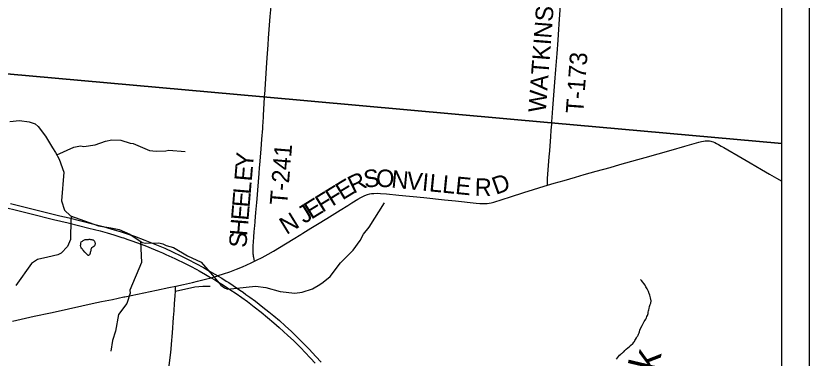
# Model space of a CAD drawing. Extents: x -5.4 to 49.9, y 13.2 to 48.4.
# Drawn here: x 30.593 to 33.165, y 43.736 to 44.845 of the extents above; entities that cross this region are included whole.
import ezdxf

# ---------------------------------------------------------------- set-up
doc = ezdxf.new("R2010")
doc.units = 0
for name, color, linetype in [('GM_X_County_Road', 7, 'Continuous'), ('GM_X_County_Road_Text', 7, 'Continuous'), ('GM_X_Minor_Lake', 7, 'Continuous'), ('GM_X_Minor_River', 7, 'Continuous'), ('GM_X_Minor_River_Text', 7, 'Continuous'), ('GM_X_Township', 7, 'Continuous'), ('GM_X_Township_Road', 7, 'Continuous'), ('GM_X_Township_Road_Text', 7, 'Continuous'), ('GM_X_US_Route', 7, 'Continuous'), ('SH_Data', 7, 'Continuous')]:
    doc.layers.add(name, color=color, linetype=linetype)

msp = doc.modelspace()

# ---------------------------------------------------------------- linework, layer by layer
at = {"layer": 'GM_X_County_Road'}
for points in [[(32.3165, 44.2958), (32.3385, 44.3026), (32.3708, 44.3117), (32.4079, 44.3222), (32.436, 44.3303), (32.4748, 44.3413), (32.5197, 44.3539), (32.5519, 44.3631), (32.6099, 44.3796), (32.6339, 44.3863), (32.6752, 44.3978), (32.7176, 44.4098), (32.7619, 44.4222), (32.7929, 44.4313), (32.8073, 44.4353), (32.8164, 44.4376), (32.8222, 44.4388), (32.8281, 44.4397), (32.8329, 44.44), (32.8376, 44.44), (32.8417, 44.4395), (32.8464, 44.4387), (32.85, 44.4378), (32.8542, 44.4365), (32.8595, 44.4344), (32.8652, 44.4317), (32.8717, 44.428), (32.8803, 44.423), (32.8884, 44.4183), (32.9479, 44.3834), (32.9742, 44.3681), (33.0108, 44.347), (33.0371, 44.3317), (33.0592, 44.319), (33.0771, 44.3087)], [(31.5172, 44.1369), (31.5231, 44.1405), (31.549, 44.1565), (31.5707, 44.1699), (31.6015, 44.1887), (31.6443, 44.2151), (31.6697, 44.2307), (31.6829, 44.2389), (31.702, 44.2507), (31.7117, 44.2563), (31.7206, 44.2608), (31.7246, 44.2626), (31.7328, 44.2657), (31.7407, 44.2677), (31.7463, 44.2688), (31.7537, 44.2698), (31.7644, 44.2701), (31.7756, 44.2696), (31.7948, 44.268), (31.8351, 44.2643), (31.916, 44.2558), (31.9828, 44.249), (32.018, 44.2455), (32.086, 44.2384), (32.0977, 44.2372), (32.107, 44.2366), (32.115, 44.2365), (32.1212, 44.2368), (32.1279, 44.2377), (32.1345, 44.239), (32.1428, 44.2413), (32.1967, 44.2583), (32.2406, 44.2722), (32.2714, 44.282), (32.3058, 44.2925), (32.3165, 44.2958)], [(31.3668, 44.0496), (31.3737, 44.0529), (31.3919, 44.0623), (31.411, 44.0727), (31.4282, 44.0826), (31.4479, 44.0944), (31.4923, 44.1218), (31.5172, 44.1369)], [(31.1112, 43.9695), (31.1368, 43.9749), (31.166, 43.981), (31.1823, 43.9847), (31.2076, 43.9912), (31.226, 43.9962), (31.2291, 43.9971), (31.2477, 44.0027), (31.2494, 44.0031), (31.2659, 44.0085), (31.287, 44.0159), (31.3085, 44.024), (31.3275, 44.0316), (31.3418, 44.0377), (31.3564, 44.0445), (31.3668, 44.0496)], [(30.9468, 43.9347), (30.9666, 43.9389), (31.0487, 43.9563), (31.0888, 43.9648), (31.1112, 43.9695)], [(30.5815, 43.8559), (30.6526, 43.8713), (30.7054, 43.883), (30.7303, 43.8884), (30.8401, 43.9127), (30.8705, 43.919), (30.9064, 43.9262), (30.9429, 43.9339), (30.9468, 43.9347)]]:
    msp.add_lwpolyline(points, dxfattribs=at)
at = {"layer": 'GM_X_Minor_Lake'}
msp.add_lwpolyline([(30.8274, 44.0679), (30.8161, 44.079), (30.8116, 44.0859), (30.8094, 44.0882), (30.8075, 44.0898), (30.8052, 44.0925), (30.8045, 44.0948), (30.8038, 44.0967), (30.803, 44.1009), (30.8031, 44.1035), (30.8031, 44.1054), (30.8035, 44.1081), (30.8051, 44.1122), (30.8066, 44.1141), (30.8085, 44.1152), (30.8112, 44.1171), (30.8131, 44.1182), (30.815, 44.119), (30.8177, 44.1197), (30.8199, 44.12), (30.8222, 44.1204), (30.8249, 44.1204), (30.8283, 44.1207), (30.8302, 44.1211), (30.8325, 44.121), (30.8347, 44.1206), (30.837, 44.1206), (30.8389, 44.1202), (30.8416, 44.1194), (30.8435, 44.119), (30.8461, 44.1171), (30.8483, 44.1144), (30.8494, 44.1106), (30.8505, 44.1079), (30.8505, 44.1053), (30.8493, 44.1026), (30.8474, 44.0996), (30.8455, 44.0977), (30.8421, 44.0955), (30.8402, 44.094), (30.8379, 44.0929), (30.8371, 44.0902), (30.8363, 44.0876), (30.8355, 44.0834), (30.8351, 44.0815), (30.8343, 44.0781), (30.8335, 44.0754), (30.8327, 44.0724), (30.8312, 44.0701), (30.8289, 44.0683), (30.8274, 44.0679)], dxfattribs=at)
at = {"layer": 'GM_X_Minor_River'}
for points in [[(30.5732, 44.5029), (30.6044, 44.5058), (30.6357, 44.5018), (30.6553, 44.4953), (30.665, 44.4868), (30.6891, 44.4548), (30.7119, 44.4168), (30.7219, 44.4018), (30.7332, 44.3803), (30.748, 44.3379), (30.7411, 44.2457), (30.7504, 44.2148), (30.7698, 44.1973), (30.8609, 44.1649), (30.9009, 44.1577), (30.9274, 44.1523), (30.9627, 44.1376), (31.0024, 44.1103), (31.0145, 44.1082), (31.057, 44.1093), (31.069, 44.1057), (31.0807, 44.1013), (31.1037, 44.094), (31.1498, 44.0673), (31.1934, 44.0472), (31.2302, 44.0051), (31.2573, 43.9727), (31.2693, 43.9634), (31.2794, 43.9598), (31.3702, 43.9688), (31.4034, 43.9651), (31.4498, 43.9521), (31.4971, 43.9467), (31.5214, 43.95), (31.5549, 43.9601), (31.5791, 43.9748), (31.5894, 43.9819), (31.6121, 44.0001), (31.6459, 44.0443), (31.6868, 44.0857), (31.7093, 44.1168), (31.7207, 44.1379), (31.7381, 44.1603), (31.788, 44.2388)], [(30.7256, 44.3948), (30.7813, 44.419), (30.803, 44.4239), (30.8128, 44.4218), (30.8504, 44.4268), (30.884, 44.4384), (30.9045, 44.4429), (30.9333, 44.4424), (30.9634, 44.432), (30.9737, 44.4318), (31.0267, 44.4088), (31.0483, 44.4069), (31.079, 44.4071), (31.0889, 44.41), (31.1422, 44.4056)], [(30.7741, 44.1958), (30.7711, 44.1859), (30.7703, 44.1206), (30.7604, 44.0972), (30.7399, 44.0756), (30.7285, 44.0701), (30.6961, 44.0627), (30.6634, 44.0549), (30.6435, 44.042), (30.5933, 43.9711)], [(30.9976, 44.1136), (31.0001, 44.0454), (30.9625, 43.9564), (30.9631, 43.9458), (30.953, 43.9125), (30.9255, 43.8773), (30.9155, 43.8236), (30.9058, 43.7926), (30.9014, 43.7589)], [(32.5411, 43.7324), (32.5438, 43.7366), (32.5473, 43.7411), (32.5508, 43.7449), (32.5542, 43.7483), (32.5573, 43.7505), (32.5592, 43.7516), (32.5623, 43.755), (32.5645, 43.7561), (32.568, 43.7603), (32.5718, 43.7644), (32.5772, 43.7693), (32.5826, 43.773), (32.5864, 43.7764), (32.594, 43.7828), (32.5952, 43.7847), (32.5971, 43.7873), (32.5987, 43.7896), (32.6006, 43.793), (32.6025, 43.7967), (32.6052, 43.8016), (32.6079, 43.8054), (32.6099, 43.8081), (32.611, 43.8103), (32.6122, 43.8133), (32.6134, 43.816), (32.6141, 43.8179), (32.6149, 43.8205), (32.6165, 43.8262), (32.6196, 43.8338), (32.6235, 43.8417), (32.6274, 43.8485), (32.6308, 43.8542), (32.6332, 43.8583), (32.6355, 43.8625), (32.6374, 43.8663), (32.6394, 43.8708), (32.6409, 43.8738), (32.6421, 43.8768), (32.6429, 43.8803), (32.6437, 43.8844), (32.6449, 43.8886), (32.6457, 43.892), (32.6465, 43.8962), (32.6481, 43.9026), (32.65, 43.9098), (32.6524, 43.9143), (32.6532, 43.9219), (32.6514, 43.9315), (32.6488, 43.9402), (32.647, 43.9452), (32.6459, 43.9471), (32.6451, 43.949), (32.6444, 43.9513), (32.6425, 43.9555), (32.6403, 43.9601), (32.6381, 43.9635), (32.6362, 43.967), (32.6336, 43.9719), (32.622, 43.9873), (32.6198, 43.9896), (32.6186, 43.99), (32.6186, 43.99)]]:
    msp.add_lwpolyline(points, dxfattribs=at)
at = {"layer": 'GM_X_Township'}
for points in [[(28.0105, 47.4437), (27.6877, 47.1657), (27.6499, 47.1327), (27.6308, 47.1161), (28.089, 46.5424), (27.3995, 45.9845), (27.4216, 45.9826), (27.5161, 45.979), (27.573, 45.9769), (27.6274, 45.9769), (27.7195, 46.0028), (27.6935, 45.0509), (27.691, 44.9621), (27.6878, 44.8437), (27.7914, 44.8377), (29.42, 44.7443), (29.8881, 44.7175), (31.3945, 44.5822), (32.3292, 44.4982), (33.0771, 44.431)], [(33.0771, 44.431), (33.0771, 47.4437), (28.0105, 47.4437)], [(33.0771, 44.431), (32.3292, 44.4982), (31.3945, 44.5822), (29.8881, 44.7175)], [(31.4373, 40.6437), (33.0771, 40.6437), (33.0771, 44.431)]]:
    msp.add_lwpolyline(points, dxfattribs=at)
at = {"layer": 'GM_X_Township_Road'}
for points in [[(31.3997, 44.586), (31.4, 44.5899), (31.4035, 44.6413), (31.4057, 44.6767), (31.4078, 44.7089), (31.4109, 44.7511), (31.4125, 44.7727), (31.4158, 44.8142), (31.4179, 44.8431), (31.4204, 44.8749)], [(32.3313, 44.5022), (32.3323, 44.5158), (32.3344, 44.5456), (32.3377, 44.5877), (32.3409, 44.6304), (32.3442, 44.6713), (32.3481, 44.7234), (32.3513, 44.7661), (32.3526, 44.7847), (32.3561, 44.8337), (32.3593, 44.8789)], [(31.3945, 44.5001), (31.3956, 44.518), (31.3972, 44.5465), (31.3979, 44.557), (31.3997, 44.586)], [(32.3265, 44.4384), (32.3276, 44.4532), (32.3292, 44.4743), (32.3307, 44.4941), (32.3313, 44.5022)], [(31.3671, 44.1581), (31.3674, 44.1618), (31.3689, 44.1792), (31.3713, 44.2077), (31.3739, 44.2399), (31.3749, 44.2516), (31.3774, 44.2801), (31.3796, 44.3073), (31.3819, 44.3346), (31.3834, 44.3532), (31.384, 44.3612), (31.3872, 44.4015), (31.3881, 44.4132), (31.3905, 44.4448), (31.3933, 44.4801), (31.3938, 44.4875), (31.3945, 44.5001)], [(32.3165, 44.2958), (32.3166, 44.2991), (32.3167, 44.3042), (32.3169, 44.3098), (32.3171, 44.3143), (32.3172, 44.3176), (32.3194, 44.346), (32.3226, 44.3882), (32.3242, 44.408), (32.3265, 44.4384)], [(31.3668, 44.0496), (31.3653, 44.0569), (31.3643, 44.0622), (31.3639, 44.0647), (31.3636, 44.0664), (31.3632, 44.0699), (31.3629, 44.0732), (31.3625, 44.0782), (31.3623, 44.0837), (31.3622, 44.0888), (31.3624, 44.0936), (31.3625, 44.0986), (31.3628, 44.103), (31.3631, 44.1092), (31.3648, 44.1309), (31.3659, 44.1433), (31.3671, 44.1581)], [(31.1061, 43.8887), (31.1078, 43.9131), (31.1095, 43.9379), (31.1109, 43.9532), (31.1108, 43.9546), (31.111, 43.9621), (31.1112, 43.9695)], [(31.1109, 43.9532), (31.1729, 43.967), (31.1988, 43.9694), (31.2234, 43.9689)], [(31.0609, 43.4913), (31.0618, 43.4981), (31.0639, 43.5135), (31.0675, 43.5425), (31.0717, 43.5733), (31.074, 43.5899), (31.0781, 43.6201), (31.0824, 43.6521), (31.0859, 43.6767), (31.0916, 43.7211), (31.0945, 43.7458), (31.0962, 43.765), (31.0975, 43.7811), (31.1004, 43.8176), (31.1045, 43.8672), (31.1061, 43.8887)]]:
    msp.add_lwpolyline(points, dxfattribs=at)
at = {"layer": 'GM_X_US_Route'}
for points in [[(30.5415, 44.228), (30.6127, 44.2105), (30.638, 44.204), (30.7147, 44.1853), (30.7623, 44.1737), (30.8293, 44.1572), (30.8661, 44.1478), (30.8888, 44.1416), (30.9103, 44.1353), (30.937, 44.1269), (30.9423, 44.1252), (30.9559, 44.1206), (30.9688, 44.1161), (30.9991, 44.1049), (31.0165, 44.0982), (31.0315, 44.0922), (31.0574, 44.0816), (31.0683, 44.0769), (31.0797, 44.072), (31.0983, 44.0634), (31.1084, 44.0586), (31.1196, 44.0532), (31.1336, 44.0464), (31.1587, 44.034), (31.1801, 44.0226), (31.1872, 44.0187), (31.2083, 44.0068), (31.2237, 43.9975), (31.226, 43.9962), (31.2377, 43.9893), (31.2498, 43.9818), (31.2657, 43.972), (31.2867, 43.9587), (31.3068, 43.9452), (31.3252, 43.9324), (31.3438, 43.9188), (31.366, 43.9019), (31.3881, 43.8846), (31.4088, 43.8678), (31.4292, 43.8505), (31.4465, 43.8354), (31.4751, 43.8095), (31.4928, 43.7929), (31.5083, 43.7777), (31.5184, 43.7676), (31.5302, 43.7555), (31.5485, 43.7361), (31.5637, 43.7196)], [(30.5755, 44.2366), (30.6322, 44.2225), (30.7354, 44.1974), (30.7656, 44.19), (30.8458, 44.1699), (30.8758, 44.1621), (30.9039, 44.1542), (30.9313, 44.146), (30.9537, 44.1387), (30.9772, 44.1306), (31.0116, 44.118), (31.033, 44.1097), (31.0543, 44.101), (31.0759, 44.0916), (31.1008, 44.0802), (31.1277, 44.0674), (31.1521, 44.0552), (31.1764, 44.0427), (31.201, 44.0294), (31.221, 44.0181), (31.2477, 44.0027), (31.249, 44.0019), (31.2611, 43.9945), (31.2753, 43.9855), (31.2831, 43.9805), (31.2977, 43.9709), (31.3193, 43.9563), (31.3295, 43.9493), (31.3391, 43.9424), (31.3511, 43.9337), (31.3696, 43.92), (31.3937, 43.9014), (31.4132, 43.886), (31.4295, 43.8726), (31.4474, 43.8572), (31.4664, 43.8402), (31.4864, 43.8217), (31.5084, 43.8007), (31.5292, 43.7801), (31.5444, 43.7646), (31.5661, 43.7415), (31.5832, 43.7227)]]:
    msp.add_lwpolyline(points, dxfattribs=at)
at = {"layer": 'SH_Data'}
msp.add_line((33.1653, 47.5483), (33.1653, 40.5483), dxfattribs=at)

# ---------------------------------------------------------------- texts
at = {"layer": 'GM_X_County_Road_Text'}
for s, rotation, p in [('S', 8.0421, (31.7244, 44.2868)), ('O', 356.0042, (31.7593, 44.2921)), ('R', 25.8424, (31.6869, 44.2678)), ('N', 354.4873, (31.8087, 44.2886)), ('V', 354.3481, (31.8585, 44.2838)), ('I', 354.3466, (31.9082, 44.2789)), ('L', 354.3466, (31.9314, 44.2766)), ('L', 354.3463, (31.9737, 44.2724)), ('E', 354.3503, (32.016, 44.2682)), ('D', 19.7797, (32.1495, 44.2645)), ('F', 31.676, (31.6193, 44.2263)), ('E', 31.343, (31.6519, 44.2464)), ('R', 358.5273, (32.0803, 44.262)), ('F', 31.6934, (31.5867, 44.2062)), ('E', 31.6915, (31.5505, 44.1839)), ('J', 31.6912, (31.5278, 44.1698)), ('N', 31.6922, (31.4704, 44.1344))]:
    msp.add_text(s, height=0.0568, rotation=rotation, dxfattribs=at).set_placement(p)
at = {"layer": 'GM_X_Minor_River_Text'}
msp.add_text('Creek', height=0.09469, rotation=76.7336, dxfattribs=at).set_placement((32.6097, 43.4217))
at = {"layer": 'GM_X_Township_Road_Text'}
for s, height, rotation, p in [('WATKINS', 0.05682, 85.7018, (32.3111, 44.5302)), ('T-173', 0.05682, 85.8358, (32.4326, 44.5271)), ('Y', 0.0568, 85.1858, (31.3612, 44.3497)), ('T-241', 0.05682, 85.2837, (31.4726, 44.2298)), ('E', 0.0568, 85.1916, (31.3577, 44.3074)), ('L', 0.0568, 85.1858, (31.3541, 44.265)), ('E', 0.0568, 85.1916, (31.3506, 44.2227)), ('E', 0.0568, 85.1858, (31.347, 44.1803)), ('H', 0.0568, 85.2881, (31.3429, 44.1305)), ('S', 0.0568, 87.2002, (31.341, 44.0927))]:
    msp.add_text(s, height=height, rotation=rotation, dxfattribs=at).set_placement(p)

doc.saveas('drawing.dxf')
